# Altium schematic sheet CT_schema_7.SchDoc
size 274 x 160 mm
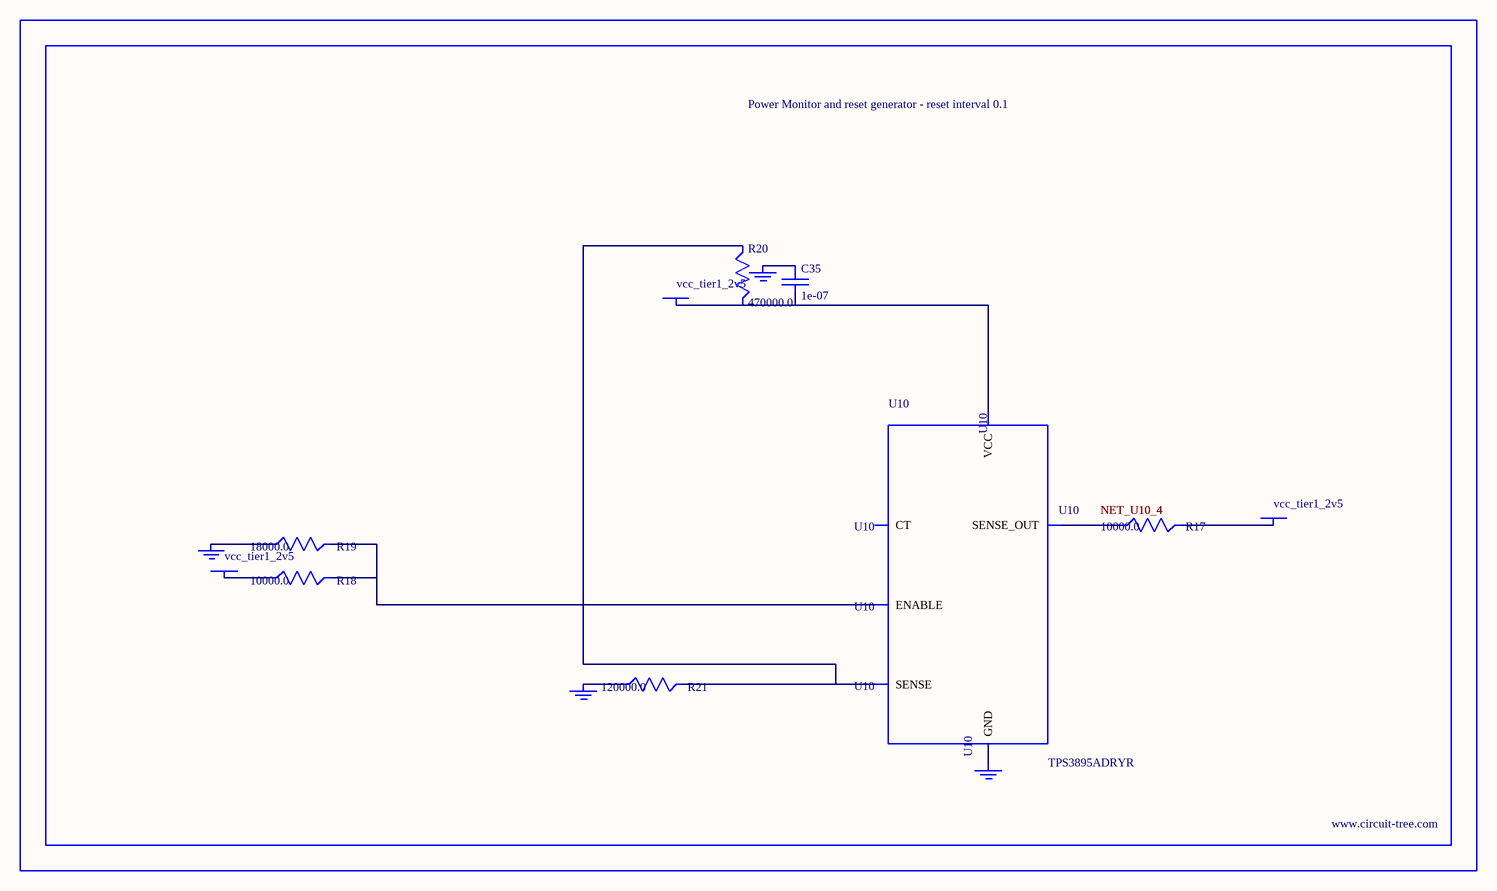
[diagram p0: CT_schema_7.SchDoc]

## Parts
BORDER6  (no value)
C35  1e-07  [C0402]
GND_INSTANCE_6_0  (no value)
GND_INSTANCE_6_1  (no value)
GND_INSTANCE_6_2  (no value)
GND_INSTANCE_6_3  (no value)
POWER_INSTANCE_6_0  vcc_tier1_2v5
POWER_INSTANCE_6_1  vcc_tier1_2v5
POWER_INSTANCE_6_2  vcc_tier1_2v5
R17  10000.0  [R0603]
R18  10000.0  [R0603]
R19  18000.0  [R0603]
R20  470000.0  [R0603]
R21  120000.0  [R0603]
U10  TPS3895ADRYR  [SON-6]

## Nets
NetC35_1: C35.1 GND_INSTANCE_6_2.0(GND)
NetC35_2: C35.2 POWER_INSTANCE_6_2.0(PWR) R20.2 U10.6(VCC)
NetGND_INSTANCE_6_0_0: GND_INSTANCE_6_0.0(GND) R19.1
NetGND_INSTANCE_6_1_0: GND_INSTANCE_6_1.0(GND) R21.1
NetGND_INSTANCE_6_3_0: GND_INSTANCE_6_3.0(GND) U10.2(GND)
NetPOWER_INSTANCE_6_0_0: POWER_INSTANCE_6_0.0(PWR) R18.1
NetPOWER_INSTANCE_6_1_0: POWER_INSTANCE_6_1.0(PWR) R17.2
NetR17_1: R17.1 U10.4(SENSE_OUT)
NetR18_2: R18.2 R19.2 U10.1(ENABLE)
NetR20_1: R20.1 R21.2 U10.3(SENSE)

Not connected (* = marked no-connect by the designer): U10 5(CT)

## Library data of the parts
BORDER6 = BORDER_PAGE6
C35 = C0402C104K3RACTU
GND_INSTANCE_6_0-GND_INSTANCE_6_3 = GND
POWER_INSTANCE_6_0-POWER_INSTANCE_6_2 = PWR
R17 R18 = RC0603JR-0710KL
R19 = RC0603JR-0718KL
R20 = RC0603JR-07470KL
R21 = RC0603JR-07120KL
